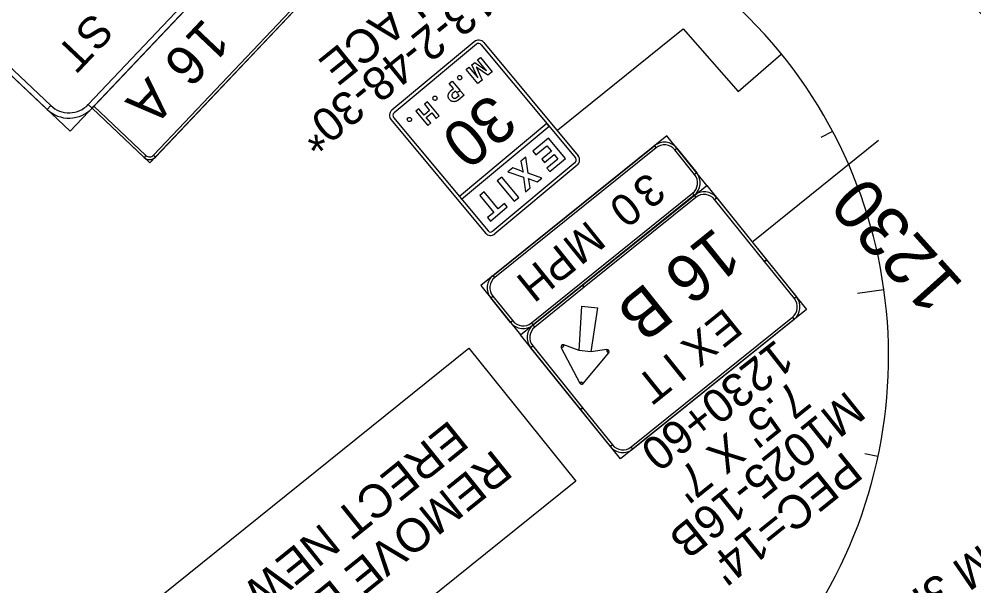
# Model space of a CAD drawing. Extents: x 2001876 to 2025694, y 804561 to 868938.
# Drawn here: x 2022302 to 2022872, y 813699 to 814037 of the extents above; entities that cross this region are included whole.
import ezdxf

# ---------------------------------------------------------------- set-up
doc = ezdxf.new("R2010")
doc.units = 0
for name, color, linetype in [('Level 30', 7, 'Continuous'), ('RD_EX_RW', 7, 'Continuous'), ('RD_PD_CLEAR ZONE', 7, 'Continuous'), ('RD_Sketch2', 7, 'Continuous'), ('TR SN EXTRUDED PANEL SIGNS - GROUND MOUNTED', 7, 'Continuous'), ('TR SN EXTRUDED PANEL SIGNS- MOUNTED OVERHEAD', 7, 'Continuous'), ('TR SN FLAT SHEET - TYPE III - FIXED SZ and MSG SIGN', 7, 'Continuous')]:
    doc.layers.add(name, color=color, linetype=linetype)

msp = doc.modelspace()

# ---------------------------------------------------------------- linework, layer by layer
at = {"layer": 'RD_PD_CLEAR ZONE'}
for centre, radius, start, end in [((2020794.27, 812071.86), 2864.79, 355.71297, 56.96135), ((2022534.17, 813835.96), 286.48, 321.9293, 46.2689)]:
    msp.add_arc(centre, radius, start, end, dxfattribs=at)
at = {"layer": 'RD_Sketch2'}
for p, q in [((2022787.26, 813970.19), (2022780.19, 813966.44)), ((2022817.9, 813875.54), (2022802.06, 813873.33)), ((2022814.33, 813776.11), (2022806.5, 813777.78))]:
    msp.add_line(p, q, dxfattribs=at)
at = {"layer": 'TR SN EXTRUDED PANEL SIGNS - GROUND MOUNTED'}
for p, q in [((2022623.18, 813971.04), (2022698.11, 814031.3)), ((2022739.78, 813904.67), (2022814.71, 813964.93)), ((2022680.88, 813961.61), (2022681.87, 813960.38)), ((2022693, 813959.17), (2022694.23, 813960.16)), ((2022706.14, 813945.36), (2022704.91, 813944.36)), ((2022703.7, 813933.23), (2022704.69, 813932)), ((2022704.69, 813932), (2022705.68, 813930.77)), ((2022716.81, 813929.56), (2022718.05, 813930.55)), ((2022585.63, 813882.98), (2022584.64, 813884.21)), ((2022583.19, 813870.86), (2022584.42, 813871.85)), ((2022765.68, 813871.33), (2022764.44, 813870.34)), ((2022596.33, 813857.04), (2022595.1, 813856.05)), ((2022763.24, 813859.2), (2022764.23, 813857.97)), ((2022608.45, 813854.6), (2022607.46, 813855.84)), ((2022609.44, 813853.37), (2022608.45, 813854.6)), ((2022607, 813841.24), (2022608.24, 813842.24)), ((2022625.33, 813841.02), (2022626.39, 813841.57)), ((2022626.39, 813841.57), (2022626.79, 813842.68)), ((2022652.59, 813839.88), (2022652.75, 813838.71)), ((2022652.75, 813838.71), (2022653.66, 813837.94)), ((2022637.43, 813820.46), (2022636.38, 813819.91)), ((2022638.34, 813819.7), (2022637.43, 813820.46)), ((2022655.87, 813783.01), (2022654.63, 813782.02)), ((2022667.99, 813780.57), (2022667, 813781.81))]:
    msp.add_line(p, q, dxfattribs=at)
for points in [[(2022688.28, 813967.57), (2022577.23, 813878.26), (2022601.05, 813848.65), (2022712.09, 813937.95), (2022688.28, 813967.57)], [(2022681.87, 813960.38), (2022585.63, 813882.98), (2022584.64, 813884.21), (2022680.88, 813961.61), (2022681.87, 813960.38)], [(2022704.91, 813944.36), (2022693, 813959.17), (2022694.23, 813960.16), (2022706.14, 813945.36), (2022704.91, 813944.36)], [(2022771.63, 813863.92), (2022660.59, 813774.62), (2022601.05, 813848.65), (2022712.09, 813937.95)], [(2022607.46, 813855.84), (2022703.7, 813933.23), (2022704.69, 813932), (2022608.45, 813854.6), (2022607.46, 813855.84)], [(2022705.68, 813930.77), (2022639.06, 813877.18), (2022638.06, 813878.42), (2022704.69, 813932), (2022705.68, 813930.77)], [(2022746.58, 813892.54), (2022716.81, 813929.56), (2022718.05, 813930.55), (2022747.82, 813893.54), (2022746.58, 813892.54)], [(2022764.44, 813870.34), (2022746.58, 813892.54), (2022747.82, 813893.54), (2022765.68, 813871.33), (2022764.44, 813870.34)], [(2022639.06, 813877.18), (2022609.44, 813853.37), (2022608.45, 813854.6), (2022638.06, 813878.42), (2022639.06, 813877.18)], [(2022584.42, 813871.85), (2022596.33, 813857.04), (2022595.1, 813856.05), (2022583.19, 813870.86), (2022584.42, 813871.85)], [(2022637.58, 813865.83), (2022647.02, 813864.81), (2022642.98, 813838.57), (2022635.9, 813839.34), (2022637.58, 813865.83)], [(2022667, 813781.81), (2022763.24, 813859.2), (2022764.23, 813857.97), (2022667.99, 813780.57), (2022667, 813781.81)], [(2022634, 813761.39), (2022115.05, 813344.03), (2022051.25, 813423.36), (2022570.2, 813840.72)], [(2022608.24, 813842.24), (2022638.01, 813805.22), (2022636.77, 813804.23), (2022607, 813841.24), (2022608.24, 813842.24)], [(2022637.43, 813820.46), (2022638.34, 813819.7), (2022653.66, 813837.94), (2022652.75, 813838.71), (2022652.59, 813839.88), (2022642.98, 813838.57), (2022635.9, 813839.34), (2022626.79, 813842.68), (2022626.39, 813841.57), (2022625.33, 813841.02), (2022636.38, 813819.91), (2022637.43, 813820.46)], [(2022638.01, 813805.22), (2022655.87, 813783.01), (2022654.63, 813782.02), (2022636.77, 813804.23), (2022638.01, 813805.22)]]:
    msp.add_lwpolyline(points, close=True, dxfattribs=at)
for centre, radius, start, end in [((2022686.83, 813954.21), 9.5, 38.8074, 128.8077), ((2022686.83, 813954.21), 7.92, 38.8074, 128.8077), ((2022698.74, 813939.4), 7.92, 308.8078, 38.8074), ((2022698.74, 813939.4), 9.5, 308.8078, 38.8074), ((2022710.64, 813924.6), 9.5, 38.8074, 128.8077), ((2022710.64, 813924.6), 7.92, 38.8074, 128.8077), ((2022590.59, 813876.81), 9.5, 128.8077, 218.8079), ((2022590.59, 813876.81), 7.92, 128.8077, 218.8079), ((2022758.27, 813865.37), 7.92, 308.8078, 38.8074), ((2022758.27, 813865.37), 9.5, 308.8078, 38.8074), ((2022602.5, 813862), 7.92, 218.8076, 308.8078), ((2022602.5, 813862), 9.5, 218.8076, 308.8078), ((2022614.41, 813847.2), 9.5, 128.8077, 218.8079), ((2022614.41, 813847.2), 7.92, 128.8077, 218.8079), ((2022626.39, 813841.57), 1.19, 69.8457, 207.6295), ((2022652.75, 813838.71), 1.19, 319.9856, 97.77), ((2022637.43, 813820.46), 1.19, 207.6295, 319.9853), ((2022662.04, 813787.98), 7.92, 218.8076, 308.8078), ((2022662.04, 813787.98), 9.5, 218.8076, 308.8078)]:
    msp.add_arc(centre, radius, start, end, dxfattribs=at)
at = {"layer": 'TR SN EXTRUDED PANEL SIGNS- MOUNTED OVERHEAD'}
for p, q in [((2022320.63, 813985.59), (2022318.45, 813983.29)), ((2022345.31, 813984.02), (2022343.01, 813986.2)), ((2022377.45, 813955.79), (2022376.36, 813954.64)), ((2022383.08, 813954.82), (2022381.93, 813955.91))]:
    msp.add_line(p, q, dxfattribs=at)
for points in [[(2022357.53, 814273.32), (2022194.26, 814100.83), (2022332.25, 813970.22), (2022495.52, 814142.71), (2022357.53, 814273.32)], [(2022343.01, 813986.2), (2022480.15, 814131.09), (2022482.45, 814128.91), (2022345.31, 813984.02), (2022343.01, 813986.2)], [(2022462.86, 814108.21), (2022345.31, 813984.02), (2022379.81, 813951.37), (2022497.36, 814075.56), (2022462.86, 814108.21)], [(2022210.24, 814090.07), (2022320.63, 813985.59), (2022318.45, 813983.29), (2022208.06, 814087.77), (2022210.24, 814090.07)], [(2022381.93, 813955.91), (2022492.95, 814073.2), (2022494.1, 814072.11), (2022383.08, 813954.82), (2022381.93, 813955.91)], [(2022346.4, 813985.17), (2022377.45, 813955.79), (2022376.36, 813954.64), (2022345.31, 813984.02), (2022346.4, 813985.17)]]:
    msp.add_lwpolyline(points, close=True, dxfattribs=at)
for centre, radius in [((2022331.51, 813997.08), 19), ((2022331.51, 813997.08), 15.83), ((2022379.63, 813958.09), 4.75), ((2022379.63, 813958.09), 3.17)]:
    msp.add_arc(centre, radius, 226.5734, 316.5736, dxfattribs=at)
at = {"layer": 'TR SN FLAT SHEET - TYPE III - FIXED SZ and MSG SIGN'}
for p, q in [((2022573.41, 814023.71), (2022524.24, 813982.75)), ((2022574.69, 814022.18), (2022525.52, 813981.21)), ((2022577.51, 814021.92), (2022633.84, 813954.31)), ((2022579.04, 814023.2), (2022635.37, 813955.59)), ((2022571.93, 814009.94), (2022573.66, 814011.38)), ((2022573.66, 814011.38), (2022580.32, 814006.78)), ((2022575.39, 814012.82), (2022577.06, 814014.21)), ((2022580.27, 814006.97), (2022575.39, 814012.82)), ((2022577.06, 814014.21), (2022584.1, 814005.76)), ((2022568.54, 814007.11), (2022570.2, 814008.5)), ((2022575.58, 813998.66), (2022568.54, 814007.11)), ((2022570.2, 814008.5), (2022575.08, 814002.64)), ((2022575.26, 814002.56), (2022571.93, 814009.94)), ((2022575.2, 814008.04), (2022574.46, 814008.66)), ((2022574.46, 814008.66), (2022574.94, 814007.82)), ((2022574.94, 814007.82), (2022578.11, 814000.77)), ((2022581.57, 814003.65), (2022575.2, 814008.04)), ((2022580.78, 814006.49), (2022580.27, 814006.97)), ((2022580.32, 814006.78), (2022580.78, 814006.49)), ((2022584.1, 814005.76), (2022581.57, 814003.65)), ((2022563.45, 814002.53), (2022563.54, 814002.83)), ((2022563.48, 814002.22), (2022563.45, 814002.53)), ((2022563.57, 814001.84), (2022563.48, 814002.22)), ((2022563.54, 814002.83), (2022563.61, 814003.01)), ((2022563.72, 814001.52), (2022563.57, 814001.84)), ((2022563.61, 814003.01), (2022563.81, 814003.17)), ((2022563.83, 814001.39), (2022563.72, 814001.52)), ((2022563.81, 814003.17), (2022564.01, 814003.34)), ((2022564.18, 814001.11), (2022563.83, 814001.39)), ((2022564.01, 814003.34), (2022564.27, 814003.44)), ((2022564.36, 814001.03), (2022564.18, 814001.11)), ((2022564.27, 814003.44), (2022564.58, 814003.47)), ((2022564.72, 814001), (2022564.36, 814001.03)), ((2022564.58, 814003.47), (2022564.82, 814003.45)), ((2022564.97, 814000.98), (2022564.72, 814001)), ((2022564.82, 814003.45), (2022564.94, 814003.44)), ((2022564.94, 814003.44), (2022565.07, 814003.43)), ((2022565.22, 814001.08), (2022564.97, 814000.98)), ((2022565.07, 814003.43), (2022565.19, 814003.42)), ((2022565.19, 814003.42), (2022565.42, 814003.27)), ((2022565.54, 814001.23), (2022565.22, 814001.08)), ((2022565.42, 814003.27), (2022565.53, 814003.14)), ((2022565.53, 814003.14), (2022565.64, 814003.01)), ((2022565.75, 814001.52), (2022565.54, 814001.23)), ((2022565.64, 814003.01), (2022565.75, 814002.87)), ((2022565.75, 814002.87), (2022565.85, 814002.62)), ((2022565.83, 814001.7), (2022565.75, 814001.52)), ((2022565.91, 814001.88), (2022565.83, 814001.7)), ((2022565.85, 814002.62), (2022565.9, 814002.43)), ((2022565.9, 814002.43), (2022565.93, 814002.12)), ((2022565.92, 814002), (2022565.91, 814001.88)), ((2022565.93, 814002.12), (2022565.92, 814002)), ((2022575.08, 814002.64), (2022575.46, 814002.05)), ((2022575.46, 814002.05), (2022575.26, 814002.56)), ((2022578.11, 814000.77), (2022575.58, 813998.66)), ((2022565.06, 813994.36), (2022562.9, 813993.31)), ((2022562.9, 813993.31), (2022565.06, 813994.36)), ((2022545.44, 813987.87), (2022543.65, 813986.37)), ((2022552.48, 813979.42), (2022545.44, 813987.87)), ((2022548.67, 813990.22), (2022548.76, 813990.52)), ((2022548.7, 813989.91), (2022548.67, 813990.22)), ((2022548.79, 813989.53), (2022548.7, 813989.91)), ((2022548.76, 813990.52), (2022548.84, 813990.7)), ((2022548.95, 813989.21), (2022548.79, 813989.53)), ((2022548.84, 813990.7), (2022549.04, 813990.86)), ((2022549.06, 813989.08), (2022548.95, 813989.21)), ((2022549.04, 813990.86), (2022549.24, 813991.03)), ((2022549.4, 813988.8), (2022549.06, 813989.08)), ((2022549.24, 813991.03), (2022549.49, 813991.13)), ((2022549.58, 813988.72), (2022549.4, 813988.8)), ((2022549.49, 813991.13), (2022549.8, 813991.16)), ((2022549.95, 813988.69), (2022549.58, 813988.72)), ((2022549.8, 813991.16), (2022550.05, 813991.14)), ((2022550.19, 813988.67), (2022549.95, 813988.69)), ((2022550.05, 813991.14), (2022550.17, 813991.13)), ((2022550.17, 813991.13), (2022550.29, 813991.12)), ((2022550.44, 813988.77), (2022550.19, 813988.67)), ((2022550.29, 813991.12), (2022550.41, 813991.11)), ((2022550.41, 813991.11), (2022550.64, 813990.96)), ((2022550.77, 813988.92), (2022550.44, 813988.77)), ((2022550.64, 813990.96), (2022550.76, 813990.83)), ((2022550.76, 813990.83), (2022550.87, 813990.7)), ((2022550.98, 813989.21), (2022550.77, 813988.92)), ((2022550.87, 813990.7), (2022550.98, 813990.56)), ((2022550.98, 813990.56), (2022551.08, 813990.31)), ((2022551.05, 813989.39), (2022550.98, 813989.21)), ((2022551.13, 813989.56), (2022551.05, 813989.39)), ((2022551.08, 813990.31), (2022551.12, 813990.12)), ((2022551.12, 813990.12), (2022551.15, 813989.81)), ((2022551.14, 813989.69), (2022551.13, 813989.56)), ((2022551.15, 813989.81), (2022551.14, 813989.69)), ((2022540.38, 813983.65), (2022538.59, 813982.16)), ((2022538.59, 813982.16), (2022545.63, 813973.7)), ((2022543.49, 813979.93), (2022540.38, 813983.65)), ((2022546.75, 813982.64), (2022543.49, 813979.93)), ((2022543.65, 813986.37), (2022546.75, 813982.64)), ((2022523.73, 813977.11), (2022580.06, 813909.5)), ((2022525.26, 813978.39), (2022581.59, 813910.78)), ((2022533.43, 813977.52), (2022533.52, 813977.82)), ((2022533.46, 813977.21), (2022533.43, 813977.52)), ((2022533.55, 813976.83), (2022533.46, 813977.21)), ((2022533.52, 813977.82), (2022533.6, 813978)), ((2022533.71, 813976.51), (2022533.55, 813976.83)), ((2022533.6, 813978), (2022533.79, 813978.16)), ((2022533.82, 813976.38), (2022533.71, 813976.51)), ((2022533.79, 813978.16), (2022533.99, 813978.33)), ((2022534.16, 813976.1), (2022533.82, 813976.38)), ((2022533.99, 813978.33), (2022534.25, 813978.43)), ((2022534.34, 813976.02), (2022534.16, 813976.1)), ((2022534.25, 813978.43), (2022534.56, 813978.46)), ((2022534.7, 813975.99), (2022534.34, 813976.02)), ((2022534.56, 813978.46), (2022534.8, 813978.44)), ((2022534.8, 813978.44), (2022534.93, 813978.43)), ((2022534.93, 813978.43), (2022535.05, 813978.42)), ((2022535.2, 813976.07), (2022534.95, 813975.97)), ((2022535.05, 813978.42), (2022535.17, 813978.41)), ((2022535.17, 813978.41), (2022535.4, 813978.26)), ((2022535.52, 813976.22), (2022535.2, 813976.07)), ((2022535.4, 813978.26), (2022535.51, 813978.13)), ((2022535.51, 813978.13), (2022535.62, 813978)), ((2022535.74, 813976.51), (2022535.52, 813976.22)), ((2022535.62, 813978), (2022535.74, 813977.86)), ((2022535.74, 813977.86), (2022535.84, 813977.61)), ((2022535.81, 813976.69), (2022535.74, 813976.51)), ((2022535.89, 813976.87), (2022535.81, 813976.69)), ((2022535.84, 813977.61), (2022535.88, 813977.42)), ((2022535.88, 813977.42), (2022535.91, 813977.11)), ((2022535.9, 813976.99), (2022535.89, 813976.87)), ((2022535.91, 813977.11), (2022535.9, 813976.99)), ((2022544.71, 813978.46), (2022547.97, 813981.18)), ((2022547.43, 813975.2), (2022544.71, 813978.46)), ((2022547.97, 813981.18), (2022550.69, 813977.92)), ((2022550.69, 813977.92), (2022552.48, 813979.42)), ((2022534.95, 813975.97), (2022534.7, 813975.99)), ((2022545.63, 813973.7), (2022547.43, 813975.2)), ((2022617.65, 813966.13), (2022608.26, 813958.3)), ((2022627.79, 813953.96), (2022617.65, 813966.13)), ((2022610.1, 813956.1), (2022616.71, 813961.61)), ((2022616.71, 813961.61), (2022619.42, 813958.35)), ((2022604.14, 813954.87), (2022601.26, 813952.47)), ((2022605.56, 813945.17), (2022604.14, 813954.87)), ((2022608.26, 813958.3), (2022610.1, 813956.1)), ((2022619.42, 813958.35), (2022613.67, 813953.56)), ((2022613.67, 813953.56), (2022615.35, 813951.55)), ((2022615.35, 813951.55), (2022621.1, 813956.34)), ((2022623.34, 813953.65), (2022616.72, 813948.14)), ((2022618.4, 813946.13), (2022627.79, 813953.96)), ((2022621.1, 813956.34), (2022623.34, 813953.65)), ((2022633.58, 813951.5), (2022584.41, 813910.53)), ((2022634.86, 813949.96), (2022585.69, 813908.99)), ((2022596.38, 813948.4), (2022593.5, 813946)), ((2022601.09, 813946.64), (2022596.38, 813948.4)), ((2022601.26, 813952.47), (2022602.12, 813947.35)), ((2022616.72, 813948.14), (2022618.4, 813946.13)), ((2022589.76, 813942.89), (2022587.08, 813940.65)), ((2022599.9, 813930.72), (2022589.76, 813942.89)), ((2022593.5, 813946), (2022602.68, 813942.78)), ((2022602.6, 813945.8), (2022601.09, 813946.64)), ((2022602.12, 813947.35), (2022602.6, 813945.8)), ((2022602.68, 813942.78), (2022603.93, 813934.07)), ((2022613.8, 813942.3), (2022605.56, 813945.17)), ((2022605.99, 813941.15), (2022605.72, 813942.06)), ((2022605.72, 813942.06), (2022606.56, 813941.63)), ((2022611.02, 813939.98), (2022613.8, 813942.3)), ((2022587.08, 813940.65), (2022597.22, 813928.48)), ((2022603.93, 813934.07), (2022606.8, 813936.47)), ((2022606.8, 813936.47), (2022605.99, 813941.15)), ((2022606.56, 813941.63), (2022611.02, 813939.98)), ((2022579.22, 813934.11), (2022576.63, 813931.95)), ((2022576.63, 813931.95), (2022585.09, 813921.79)), ((2022587.68, 813923.95), (2022579.22, 813934.11)), ((2022597.22, 813928.48), (2022599.9, 813930.72)), ((2022583.03, 813916.67), (2022593.1, 813925.05)), ((2022591.42, 813927.06), (2022587.68, 813923.95)), ((2022593.1, 813925.05), (2022591.42, 813927.06)), ((2022585.09, 813921.79), (2022581.36, 813918.68)), ((2022581.36, 813918.68), (2022583.03, 813916.67))]:
    msp.add_line(p, q, dxfattribs=at)
for points in [[(2022698.11, 814031.3), (2022730.95, 813993.95), (2022756.35, 814016.16)], [(2022559.05, 813994.13), (2022560.92, 813995.69), (2022558.42, 813998.68), (2022560.22, 814000.18), (2022564.76, 813994.73)], [(2022563.6, 813988.68), (2022563.14, 813988.41), (2022562.76, 813988.2), (2022562.57, 813988.16), (2022562.31, 813988.06), (2022562.12, 813988.01), (2022561.94, 813987.97), (2022561.62, 813987.93), (2022561.31, 813987.9), (2022561.07, 813987.92), (2022560.83, 813987.95), (2022560.58, 813987.97), (2022560.28, 813988.06), (2022559.98, 813988.15), (2022559.63, 813988.3), (2022559.4, 813988.44), (2022559.16, 813988.59), (2022559.11, 813988.66), (2022558.76, 813988.93), (2022558.54, 813989.2), (2022558.38, 813989.4), (2022558.16, 813989.79), (2022558.06, 813990.04), (2022557.96, 813990.3), (2022557.92, 813990.49), (2022557.88, 813990.67), (2022557.84, 813990.98), (2022557.81, 813991.3), (2022557.83, 813991.54), (2022557.85, 813991.78), (2022557.88, 813992.03), (2022557.97, 813992.33), (2022558.05, 813992.63), (2022558.13, 813992.8), (2022558.21, 813992.98), (2022558.35, 813993.21), (2022558.5, 813993.45), (2022558.71, 813993.73), (2022559.05, 813994.13)], [(2022562.9, 813993.31), (2022562.14, 813994.22), (2022560.67, 813993)], [(2022565.06, 813994.36), (2022567.26, 813991.73), (2022563.6, 813988.68)], [(2022560.67, 813993), (2022560.54, 813992.89), (2022560.33, 813992.6), (2022560.18, 813992.37), (2022560.11, 813992.19), (2022560.02, 813991.89), (2022559.99, 813991.65), (2022559.98, 813991.53), (2022560.02, 813991.22), (2022560.12, 813990.96), (2022560.27, 813990.64), (2022560.38, 813990.51), (2022560.73, 813990.23), (2022560.96, 813990.09), (2022561.26, 813990), (2022561.5, 813989.98), (2022561.75, 813989.95), (2022561.94, 813990), (2022562.12, 813990.04), (2022562.31, 813990.09), (2022562.7, 813990.3), (2022562.77, 813990.35), (2022562.83, 813990.41)], [(2022562.83, 813990.41), (2022564.3, 813991.63), (2022563.37, 813992.74)]]:
    msp.add_lwpolyline(points, dxfattribs=at)
msp.add_lwpolyline([(2022616.75, 813974.82), (2022564.51, 813931.29), (2022565.79, 813929.75), (2022618.03, 813973.28)], close=True, dxfattribs=at)
for centre, radius, start, end in [((2022575.97, 814020.64), 4, 39.8006, 129.8006), ((2022575.97, 814020.64), 2, 39.8006, 129.8006), ((2022526.8, 813979.67), 4, 129.8006, 219.8006), ((2022526.8, 813979.67), 2, 129.8006, 219.8006), ((2022632.3, 813953.03), 2, 309.8006, 39.8006), ((2022632.3, 813953.03), 4, 309.8006, 39.8006), ((2022583.13, 813912.06), 4, 219.8006, 309.8006), ((2022583.13, 813912.06), 2, 219.8006, 309.8006)]:
    msp.add_arc(centre, radius, start, end, dxfattribs=at)

# ---------------------------------------------------------------- texts
at = {"layer": 'Level 30'}
for s, p in [('M1025-16B', (2022795.91, 813815.94)), ("PEC=14'", (2022794.1, 813779.84))]:
    msp.add_text(s, height=20, rotation=218.8076, dxfattribs=at).set_placement(p)
at = {"layer": 'RD_EX_RW'}
msp.add_text('1230', height=30, rotation=131.9244, dxfattribs=at).set_placement((2022866.25, 813878.61))
at = {"layer": 'TR SN EXTRUDED PANEL SIGNS - GROUND MOUNTED'}
for s, height, rotation, p in [('3', 19, 218.8076, (2022677.37, 813946.6)), ('0', 19, 218.8076, (2022663.36, 813935.33)), ('M', 19, 218.8076, (2022641.36, 813917.64)), ('1', 28.5, 218.8076, (2022717.28, 813913.68)), ('P', 19, 218.8076, (2022623.99, 813903.67)), ('6', 28.5, 218.8076, (2022701.19, 813900.74)), ('H', 19, 218.8076, (2022611.43, 813893.57)), ('B', 28.5, 218.8076, (2022676.37, 813880.77)), ('E', 19, 218.8076, (2022722.99, 813865.44)), ('X', 19, 218.8076, (2022708.69, 813853.94)), ('1230+60', 20, 218.0799, (2022753.67, 813846.6)), ('I', 19, 218.8076, (2022689.86, 813838.8)), ('T', 19, 218.8076, (2022680.33, 813831.13)), ("7.5' X 7'", 20, 218.8076, (2022763.3, 813822.32)), ('ERECT NEW I-BEAM POSTS AND NEW SIGN.', 20, 218.8076, (2022558.91, 813798.41)), ('REMOVE EXISTING I-BEAM POSTS AND SIGN.', 20, 218.8076, (2022585, 813780.89)), ('OM 3.5L-24', 20, 214.4426, (2022892.78, 813736.01))]:
    msp.add_text(s, height=height, rotation=rotation, dxfattribs=at).set_placement(p)
at = {"layer": 'TR SN EXTRUDED PANEL SIGNS- MOUNTED OVERHEAD'}
for s, height, rotation, p in [('REPLACE', 20, 218.8146, (2022576.7, 814090.43)), ('W13-2-48-30*', 20, 218.8146, (2022595.86, 814075.59)), ('S', 19, 226.5734, (2022345.7, 814042.01)), ('1', 23.75, 226.5734, (2022412.18, 814038.55)), ('T', 19, 226.5734, (2022333.3, 814028.91)), ('6', 23.75, 226.5734, (2022398.9, 814024.51)), ('A', 23.75, 226.5734, (2022378.84, 814003.32))]:
    msp.add_text(s, height=height, rotation=rotation, dxfattribs=at).set_placement(p)
at = {"layer": 'TR SN FLAT SHEET - TYPE III - FIXED SZ and MSG SIGN'}
msp.add_text('30', height=27.648, rotation=219.8006, dxfattribs=at).set_placement((2022583.38, 813993.86))

doc.saveas('drawing.dxf')
